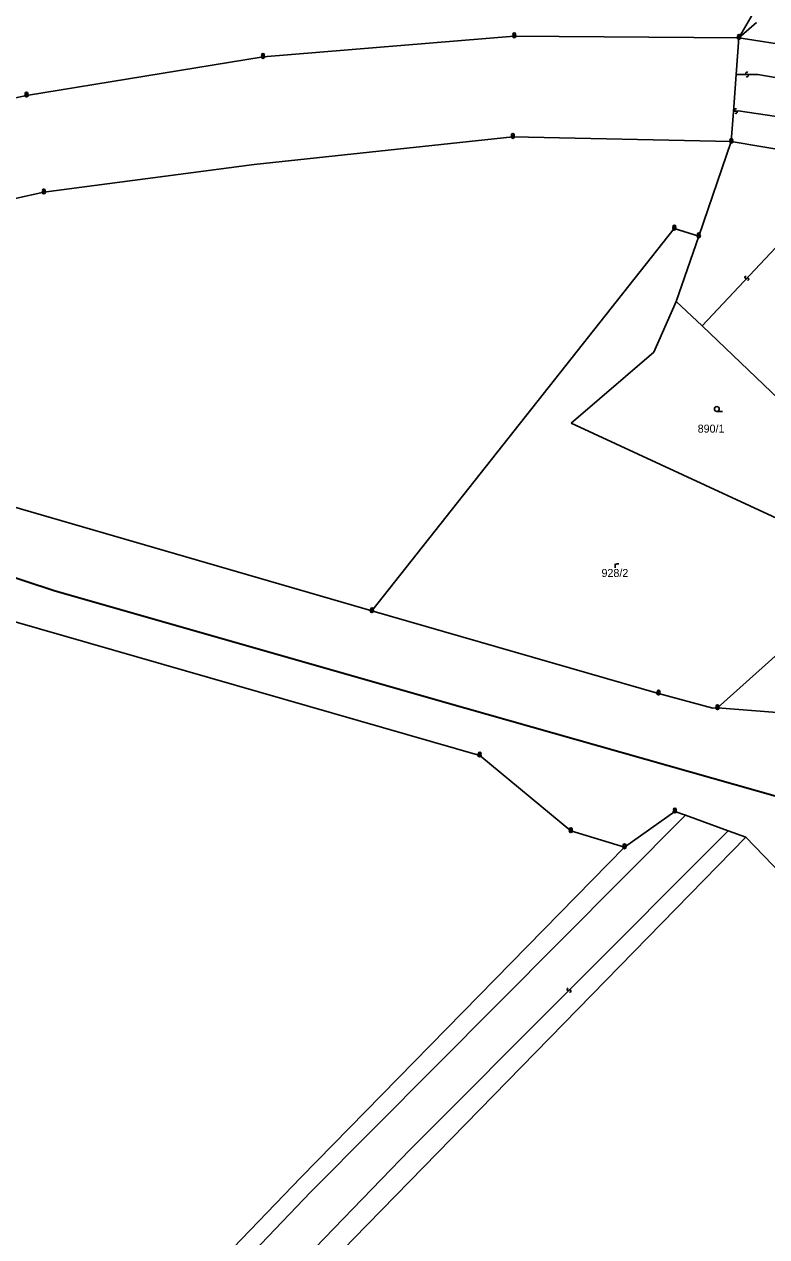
# Model space of a CAD drawing. Extents: x -871901 to -870967, y -1075952 to -1074892.
# Drawn here: x -871287.2 to -871194.5, y -1075441.5 to -1075290 of the extents above; entities that cross this region are included whole.
import ezdxf

# ---------------------------------------------------------------- set-up
doc = ezdxf.new("R2010")
doc.units = 0
doc.header["$LTSCALE"] = 0.4
for name, color, linetype, lineweight in [('1', 7, 'Continuous', 25), ('10', 7, 'Continuous', 35), ('24', 7, 'Continuous', 25), ('25', 7, 'Continuous', 25), ('4', 7, 'Continuous', 25)]:
    doc.layers.add(name, color=color, linetype=linetype, lineweight=lineweight)
doc.layers.add('18', color=7, linetype='Continuous')

msp = doc.modelspace()

# ---------------------------------------------------------------- linework, layer by layer
at = {"layer": '1'}
for p, q in [((-871197.94, -1075291.72), (-871178.28, -1075294.81)), ((-871317.28, -1075305.51), (-871286.96, -1075298.91)), ((-871198.89, -1075304.69), (-871190.75, -1075306.03)), ((-871243.8, -1075363.33), (-871206.01, -1075315.54)), ((-871206.01, -1075315.54), (-871202.96, -1075316.49)), ((-871208.57, -1075330.98), (-871205.8, -1075324.68)), ((-871205.8, -1075324.68), (-871202.55, -1075327.7)), ((-871202.55, -1075327.7), (-871185.37, -1075344.12)), ((-871218.91, -1075339.87), (-871208.57, -1075330.98)), ((-871218.91, -1075339.87), (-871180.67, -1075357.59)), ((-871243.8, -1075363.33), (-871207.98, -1075373.63)), ((-871207.98, -1075373.63), (-871201.2, -1075375.48))]:
    msp.add_line(p, q, dxfattribs=at)
for points in [[(-871590.36, -1075167.06), (-871564.6, -1075180.17), (-871498.95, -1075191.88), (-871324.15, -1075210.15), (-871152.53, -1075228.75), (-871169.32, -1075257.9), (-871185.72, -1075270.67), (-871197.94, -1075291.72)], [(-871198.89, -1075304.69), (-871198.62, -1075300.91), (-871198.28, -1075296.29), (-871197.94, -1075291.72), (-871195.74, -1075289.82)], [(-871286.96, -1075298.91), (-871257.41, -1075294.08), (-871226.01, -1075291.51), (-871197.94, -1075291.72)], [(-871198.89, -1075304.69), (-871226.19, -1075304.09), (-871258.51, -1075307.55), (-871284.79, -1075311.01)], [(-871205.8, -1075324.68), (-871202.96, -1075316.49), (-871198.89, -1075304.69)], [(-871324.12, -1075317.6), (-871315.25, -1075317.74), (-871308.94, -1075316.35), (-871284.79, -1075311.01)], [(-871324.12, -1075317.6), (-871338.12, -1075333.63), (-871324.93, -1075338.1), (-871290.33, -1075349.84), (-871243.8, -1075363.33)], [(-871212.24, -1075392.84), (-871218.94, -1075390.82), (-871230.33, -1075381.38), (-871303.93, -1075360.22), (-871330.24, -1075349.97), (-871352.11, -1075340.43), (-871367.76, -1075336.32)], [(-871201.2, -1075375.48), (-871200.62, -1075375.46), (-871180.67, -1075357.59)], [(-871200.62, -1075375.46), (-871193.17, -1075376.03), (-871185.81, -1075376.53), (-871183.42, -1075376.69)], [(-871212.24, -1075392.84), (-871205.94, -1075388.38), (-871204.62, -1075388.86), (-871199.28, -1075390.81), (-871197.08, -1075391.62), (-871190.41, -1075398.53), (-871175.19, -1075397.63)], [(-871197.08, -1075391.62), (-871246.11, -1075441.8), (-871278.54, -1075475.47), (-871283.35, -1075480.46), (-871309.29, -1075507.4), (-871370.19, -1075570.62), (-871394.77, -1075599.26), (-871418.31, -1075635.76), (-871432.83, -1075664.02), (-871448.97, -1075707.84), (-871454.61, -1075721.79)], [(-871462.11, -1075711.44), (-871457.75, -1075700.95), (-871441.61, -1075657.13), (-871427.67, -1075629.24), (-871402.35, -1075592.63), (-871377.15, -1075563.45), (-871252.68, -1075434.13), (-871212.24, -1075392.84)]]:
    msp.add_lwpolyline(points, dxfattribs=at)
at = {"layer": '10'}
msp.add_lwpolyline([(-871303.26, -1075354.3), (-871283.38, -1075360.82), (-871232.19, -1075375.42), (-871192.83, -1075386.61), (-871111.78, -1075409.09), (-871082.8, -1075416.75), (-871053.48, -1075423.53)], dxfattribs=at)
at = {"layer": '24'}
for centre, radius in [((-871226.0095, -1075291.5095), 0.2005), ((-871226.0095, -1075291.5095), 0.00851), ((-871197.9395, -1075291.7195), 0.2005), ((-871197.9395, -1075291.7195), 0.00851), ((-871257.4095, -1075294.0795), 0.2005), ((-871257.4095, -1075294.0795), 0.00851), ((-871286.9595, -1075298.9095), 0.2005), ((-871286.9595, -1075298.9095), 0.00851), ((-871226.1895, -1075304.0895), 0.2005), ((-871226.1895, -1075304.0895), 0.00851), ((-871198.8895, -1075304.6895), 0.2005), ((-871198.8895, -1075304.6895), 0.00851), ((-871284.7895, -1075311.0095), 0.2005), ((-871284.7895, -1075311.0095), 0.00851), ((-871206.0095, -1075315.5395), 0.2005), ((-871206.0095, -1075315.5395), 0.00851), ((-871202.9595, -1075316.4895), 0.2005), ((-871202.9595, -1075316.4895), 0.00851), ((-871243.7995, -1075363.3295), 0.2005), ((-871243.7995, -1075363.3295), 0.00851), ((-871207.9795, -1075373.6295), 0.2005), ((-871207.9795, -1075373.6295), 0.00851), ((-871200.6195, -1075375.4595), 0.2005), ((-871200.6195, -1075375.4595), 0.00851), ((-871230.3295, -1075381.3795), 0.2005), ((-871230.3295, -1075381.3795), 0.00851), ((-871205.9395, -1075388.3795), 0.2005), ((-871205.9395, -1075388.3795), 0.00851), ((-871218.9395, -1075390.8195), 0.2005), ((-871218.9395, -1075390.8195), 0.00851), ((-871212.2395, -1075392.8395), 0.2005), ((-871212.2395, -1075392.8395), 0.00851)]:
    msp.add_circle(centre, radius, dxfattribs=at)
for centre in [(-871226.0098, -1075291.2836), (-871197.9398, -1075291.4936), (-871257.4098, -1075293.8536), (-871286.9598, -1075298.6836), (-871226.1898, -1075303.8636), (-871198.8898, -1075304.4636), (-871284.7898, -1075310.7836), (-871206.0098, -1075315.3136), (-871202.9598, -1075316.2636), (-871243.7998, -1075363.1036), (-871207.9798, -1075373.4036), (-871200.6198, -1075375.2336), (-871230.3298, -1075381.1536), (-871205.9398, -1075388.1536), (-871218.9398, -1075390.5936), (-871212.2398, -1075392.6136)]:
    msp.add_arc(centre, 0.1746, 328.19485, 209.95045, dxfattribs=at)
at = {"layer": '25'}
for p, q in [((-871200.7, -1075338.4), (-871199.999, -1075338.4)), ((-871213.42, -1075357.96), (-871213.42, -1075357.439))]:
    msp.add_line(p, q, dxfattribs=at)
msp.add_lwpolyline([(-871213.42, -1075357.603), (-871213.348, -1075357.532), (-871213.269, -1075357.487), (-871213.157, -1075357.457), (-871213.052, -1075357.438), (-871212.939, -1075357.431)], dxfattribs=at)
msp.add_circle((-871200.6995, -1075338.0995), 0.3005, dxfattribs=at)
for centre, radius, start, end in [((-871196.9273, -1075296.1528), 0.1473, 36.51322, 268.833), ((-871196.9325, -1075296.4474), 0.1474, 216.48449, 89.22408), ((-871198.3484, -1075300.7239), 0.1473, 45.43361, 277.0306), ((-871198.3106, -1075301.016), 0.1473, 225.00179, 98.07797), ((-871197.0559, -1075321.6675), 0.1474, 84.5839, 316.10422), ((-871196.8437, -1075321.8723), 0.1475, 264.17576, 136.75989), ((-871219.283, -1075410.6343), 0.1476, 82.20047, 313.51524), ((-871219.0763, -1075410.8443), 0.1471, 262.31548, 135.00108)]:
    msp.add_arc(centre, radius, start, end, dxfattribs=at)
at = {"layer": '4'}
for p, q in [((-871198.28, -1075296.29), (-871195.57, -1075296.31)), ((-871195.57, -1075296.31), (-871185.5, -1075298.06)), ((-871198.62, -1075300.91), (-871198.04, -1075300.83)), ((-871198.04, -1075300.83), (-871188.7, -1075302.25)), ((-871202.55, -1075327.7), (-871191.36, -1075315.85))]:
    msp.add_line(p, q, dxfattribs=at)
for points in [[(-871456.27, -1075704.47), (-871441.17, -1075661.93), (-871431.74, -1075641.73), (-871423.61, -1075627.58), (-871411.59, -1075609.37), (-871394.86, -1075586.88), (-871326.72, -1075514.76), (-871291.4, -1075477.73), (-871251.44, -1075435.93), (-871204.62, -1075388.86)], [(-871199.28, -1075390.81), (-871239.07, -1075430.66), (-871281.77, -1075474.85), (-871340.49, -1075536.51), (-871370.95, -1075568.72), (-871393.73, -1075593.84), (-871411.43, -1075617.88), (-871422.7, -1075636.35), (-871430.78, -1075652.09), (-871436.26, -1075664.18), (-871439.7, -1075674.21), (-871456.47, -1075719.22)]]:
    msp.add_lwpolyline(points, dxfattribs=at)

# ---------------------------------------------------------------- texts
at = {"layer": '18'}
for s, p in [('890/1', (-871203.09, -1075341.05)), ('928/2', (-871215.11, -1075359.09))]:
    msp.add_text(s, height=1, dxfattribs=at).set_placement(p)

doc.saveas('drawing.dxf')
